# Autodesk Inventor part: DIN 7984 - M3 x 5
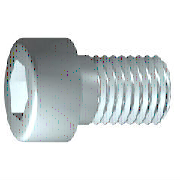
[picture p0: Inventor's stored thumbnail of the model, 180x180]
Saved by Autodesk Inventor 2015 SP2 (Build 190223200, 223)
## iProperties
IsCustomPart: 0
Created: 2012-02
Part Number: DIN 7984 - M3 x 5
Material: Stahl, weich
Description: Zylinderkopfschraube
Document SubType Name: Modeling
Standard: DIN 7984
Designer: rYan
Standard Revision: 1985
Standards Organization: DIN
Language: de-DE
Size Designation: M3 x 5
Categories: <MemberInstance><Categories><Category DisplayName="Verbindungselemente" InternalName="e4da775c-781d-43d5-af7c-5136215cf5a6" Mnemonic="FSTN"><Category DisplayNam
Density: 7.85 g/cm^3
Mass: 0.596913 g
Surface Area: 1.36052 cm^2
Volume: 0.0760398 cm^3
Appearance: Halbpoliert
Author: rYan
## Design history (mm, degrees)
sketch "Skizze1"
  geometry: L1 (0.167, 0)-(5, 0); L2 (5, 0)-(5, 1.5); L3 (5, 1.5)-(1.5, 1.5); L4 (1.5, 1.5)-(1.193, 1.5); L5 (1.193, 1.5)-(0, 1.5); L6 (0, 1.5)-(0, 2.75); L7 (0, 2.75)-(-2, 2.75); L8 (-2, 2.75)-(-2, 1.155); L9 (-2, 1.155)-(-0.5, 1.155); L10 (-0.5, 1.155)-(0.167, 0); L11 (-3.4, 0)-(6.4, 0) reference; L12 (0, -0.55)-(0, 3.3) reference; L13 (1.5, 1.5)-(0, 1.5)
  constraints: 22 end point, 6 parallel, 2 collinear, 2 perpendicular, 1 horizontal, 1 point on line
  dimensions: "d1" = 3.5 distance from line of L3.end L2 (= GEL); "d2" = 0.30683 distance of L4.end L3.end (computed from GAL); "d3" = 2 distance between parallel lines of L8 L6 (= KOH); "d4" = 1.5 distance of L8.end L9.end (= INTI); "d5" = 60 deg angle of L10 L1; "d6" = 3 diameter of L3 L1 (= GD); "d7" = 3 diameter of L5 L1 (= BDM); "d8" = 2.3094 diameter of L9 L1 (= 1.1547 x SW); "d9" = 5.5 diameter of L7 L1 (= KOD); "d26" = 5 distance between parallel lines of L12 L2 (= NLG)
revolve "Körper" sketch "Skizze1" stored, may be unused: angle "d10" = 90 deg
sketch "Skizze2"
  geometry: L1 (0, -3.85)-(0, 3.85) reference; L2 (-3.85, 0)-(3.85, 0) reference; L3 (1.155, 0)-(0.577, -1); L4 (0.577, -1)-(-0.577, -1); L5 (-0.577, -1)-(-1.155, 0); L6 (-1.155, 0)-(-0.577, 1); L7 (-0.577, 1)-(0.577, 1); L8 (0.577, 1)-(1.155, 0); 2 further points
  constraints: 12 end point, 1 coincident, 1 horizontal alignment, 1 point on line, 12 other
extrude "Loch" join sketch "Skizze2" stored distance "d11" = 10; taper "d12" = 0 deg
workplane "Work Plane1"
fillet "Fillet2" dims "d30" = 0.1 (= R)
body "Solid1"
fillet "Rundung1" dims "d17" = 0.3 (= RR)
feature "Gewinde" dims "d13" = 3.5 (= GEL), "d14" = 0
chamfer "Fase1" distance "d15" = 0.30673 (= -0.5 x SPD + 0.5 x GD); stored, may be unused: second distance "d16" = 0.30673 (= GUL), angle "d27" = 45 deg
other parameters: "GD" = 3 (= NND) [user parameter; used in 2 equation terms], "NLG" = 5 [user parameter; used in 1 equation term], "GEL" = 3.5 [user parameter; used in 2 equation terms], "KOD" = 5.5 [user parameter; used in 1 equation term], "KOH" = 2 [user parameter; used in 1 equation term], "INTI" = 1.5 [user parameter; used in 1 equation term], "GAL" = 0.30673 (= 0.61345 x PTC) [user parameter; used in 1 equation term], "GUL" = 0.30673 (= 0.61345 x PTC) [user parameter; used in 1 equation term], "BDM" = 3 (= NND) [user parameter; used in 1 equation term], "SW" = 2 [user parameter; used in 2 equation terms], "RR" = 0.3 [user parameter; used in 1 equation term], "SPD" = 2.38655 (= NND - 1.2269 x PTC) [user parameter; used in 1 equation term], "d19" = 0, "d28" = 0, "d29" = 0, "R" = 0.1 [user parameter; used in 1 equation term], "TOA" = 30 deg [user parameter], "GD1" = 2.38655 (= THREADDIA - 1.2269 x PTC) [user parameter], "THREADDIA" = 3 [user parameter; used in 1 equation term], "FAWI" = 45 deg [user parameter], "ANG" = 120 deg [user parameter], "PTC" = 0.5 [user parameter; used in 5 equation terms], "NND" = 3 [user parameter; used in 3 equation terms], "E0" = 2.31 (= 1.155 x SW) [user parameter]
